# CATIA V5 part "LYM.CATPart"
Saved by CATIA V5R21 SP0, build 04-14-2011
Part number: LYM.SLDPRT
Bounding box of the stored display mesh (mm): x -1.375 to 1.375, y -1 to 1, z -0.25 to 0.45
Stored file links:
  C:\Users\user\Desktop\CATIA文件\LYM\LYM.CATPart
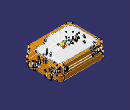
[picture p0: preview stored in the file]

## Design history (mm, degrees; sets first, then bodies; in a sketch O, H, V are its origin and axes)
AxisSystem1: origin (0.0446, -0.0275, 0.449), X (0, -1, 0), Y (1, 0, 0), Z (0, 0, 1)
Set1
  DatumSurface1 to DatumSurface42
  Circle1: stored without definition
  Line1: stored without definition
  Circle2: stored without definition
  Line2: stored without definition
  Circle3: stored without definition
  Line3: stored without definition
  Circle4: stored without definition
  Line4 to Line12: stored without definition
  Circle5: stored without definition
  Line13 to Line27: stored without definition
  Circle6: stored without definition
  Line28: stored without definition
  Circle7: stored without definition
  Line29: stored without definition
  Circle8: stored without definition
  Line30 to Line32: stored without definition
  Circle9: stored without definition
  Line33: stored without definition
  Circle10: stored without definition
  Line34 to Line40: stored without definition
  Circle11: stored without definition
  Line41: stored without definition
  Circle12: stored without definition
  Line42: stored without definition
  Circle13: stored without definition
  Line43: stored without definition
  Circle14: stored without definition
  Line44: stored without definition
  Line45: stored without definition
  Circle15: stored without definition
  Line46: stored without definition
  Circle16: stored without definition
  Line47: stored without definition
  Circle17: stored without definition
  Line48: stored without definition
  Circle18: stored without definition
  Line49: stored without definition
  Circle19: stored without definition
  Line50: stored without definition
  Circle20: stored without definition
  Line51: stored without definition
  Circle21: stored without definition
  Line52: stored without definition
  Circle22: stored without definition
  Line53 to Line56: stored without definition
  Circle23: stored without definition
  Line57 to Line59: stored without definition
  Circle24: stored without definition
  Line60 to Line62: stored without definition
  Circle25: stored without definition
  Line63 to Line65: stored without definition
  Circle26: stored without definition
  Line66 to Line69: stored without definition
  Circle27: stored without definition
  Line70 to Line72: stored without definition
  Circle28: stored without definition
  Line73: stored without definition
  Line74: stored without definition
  Circle29: stored without definition
  Line75 to Line77: stored without definition
  Circle30: stored without definition
  Line78 to Line82: stored without definition
  Circle31: stored without definition
  Line83: stored without definition
  Line84: stored without definition
  Circle32: stored without definition
  Line85 to Line88: stored without definition
  DatumSurface43 to DatumSurface82
  Line89 to Line104: stored without definition
  Circle33: stored without definition
  Line105 to Line122: stored without definition
  Circle34: stored without definition
  Circle35: stored without definition
  Line123: stored without definition
  Circle36: stored without definition
  Line124 to Line127: stored without definition
  Circle37: stored without definition
  Line128: stored without definition
  Circle38: stored without definition
  Line129 to Line135: stored without definition
  Circle39: stored without definition
  Line136: stored without definition
  Circle40: stored without definition
  Line137: stored without definition
  Circle41: stored without definition
  Line138: stored without definition
  Circle42: stored without definition
  Line139: stored without definition
  Line140: stored without definition
  Circle43: stored without definition
  Line141: stored without definition
  Circle44: stored without definition
  Line142: stored without definition
  Circle45: stored without definition
  Line143: stored without definition
  Circle46: stored without definition
  Line144: stored without definition
  Circle47: stored without definition
  Line145: stored without definition
  Circle48: stored without definition
  Line146: stored without definition
  Circle49: stored without definition
  Line147: stored without definition
  Circle50: stored without definition
  Line148: stored without definition
  Circle51: stored without definition
  Line149: stored without definition
  Circle52: stored without definition
  Line150: stored without definition
  Circle53: stored without definition
  Line151: stored without definition
  Circle54: stored without definition
  Line152: stored without definition
  Circle55: stored without definition
  Line153: stored without definition
  Circle56: stored without definition
  Line154: stored without definition
  Circle57: stored without definition
  Line155: stored without definition
  Circle58: stored without definition
  Line156 to Line176: stored without definition
  DatumSurface83 to DatumSurface188
  Line177: stored without definition
  Circle59: stored without definition
  Line178: stored without definition
  Circle60: stored without definition
  Line179: stored without definition
  Circle61: stored without definition
  Line180: stored without definition
  Circle62: stored without definition
  Line181 to Line197: stored without definition
  Circle63: stored without definition
  Line198 to Line214: stored without definition
  Circle64: stored without definition
  Line215: stored without definition
  Circle65: stored without definition
  Line216: stored without definition
  Circle66: stored without definition
  Line217 to Line220: stored without definition
  Circle67: stored without definition
  Circle68: stored without definition
  Line221 to Line227: stored without definition
  Circle69: stored without definition
  Line228: stored without definition
  Circle70: stored without definition
  Line229: stored without definition
  Circle71: stored without definition
  Line230: stored without definition
  Circle72: stored without definition
  Line231 to Line235: stored without definition
  Circle73: stored without definition
  Line236 to Line238: stored without definition
  Circle74: stored without definition
  Line239: stored without definition
  Circle75: stored without definition
  Line240 to Line242: stored without definition
  Circle76: stored without definition
  Line243 to Line249: stored without definition
  Circle77: stored without definition
  Circle78: stored without definition
  Line250 to Line256: stored without definition
  Circle79 to Circle81: stored without definition
  Line257: stored without definition
  Circle82: stored without definition
  Circle83: stored without definition
  Line258: stored without definition
  Circle84: stored without definition
  Line259 to Line266: stored without definition
  Circle85: stored without definition
  Line267 to Line281: stored without definition
  Circle86: stored without definition
  Line282: stored without definition
  Line283: stored without definition
  Circle87: stored without definition
  Line284: stored without definition
  Circle88: stored without definition
  Line285 to Line288: stored without definition
  Circle89: stored without definition
  Circle90: stored without definition
  Line289 to Line295: stored without definition
  Circle91: stored without definition
  Line296: stored without definition
  Circle92: stored without definition
  Line297: stored without definition
  Circle93: stored without definition
  Line298: stored without definition
  Circle94: stored without definition
  Line299 to Line302: stored without definition
  Circle95: stored without definition
  Line303 to Line305: stored without definition
  Circle96: stored without definition
  Line306 to Line309: stored without definition
  Circle97: stored without definition
  Line310: stored without definition
  Circle98: stored without definition
  Line311: stored without definition
  Circle99: stored without definition
  Line312: stored without definition
  Circle100: stored without definition
  Line313 to Line316: stored without definition
  Circle101: stored without definition
  Line317 to Line319: stored without definition
  Circle102: stored without definition
  Line320 to Line325: stored without definition
  Circle103: stored without definition
  Circle104: stored without definition
  Line326 to Line332: stored without definition
  Circle105: stored without definition
  Line333: stored without definition
  DatumCurve1
  Line334: stored without definition
  DatumCurve2
  Line335: stored without definition
  Line336: stored without definition
  DatumCurve3
  Line337: stored without definition
  DatumCurve4
  Line338 to Line340: stored without definition
  Circle106: stored without definition
  Circle107: stored without definition
  Line341: stored without definition
  DatumCurve5
  Line342: stored without definition
  DatumCurve6
  Line343: stored without definition
  Line344: stored without definition
  Circle108: stored without definition
  Line345: stored without definition
  DatumCurve7
  Line346: stored without definition
  DatumCurve8
  Line347 to Line360: stored without definition
  DatumCurve9
  Line361: stored without definition
  DatumCurve10
  Line362: stored without definition
  DatumCurve11
  Line363: stored without definition
  DatumCurve12
  Line364: stored without definition
  DatumCurve13
  Line365: stored without definition
  DatumCurve14
  Line366 to Line371: stored without definition
  DatumCurve15
  Line372 to Line375: stored without definition
  DatumCurve16
  Line376 to Line378: stored without definition
  DatumCurve17
  Line379 to Line381: stored without definition
  DatumCurve18
  Line382 to Line384: stored without definition
  DatumCurve19
  Line385 to Line387: stored without definition
  DatumCurve20
  Line388 to Line400: stored without definition
  DatumSurface189
  DatumCurve21
  Line401: stored without definition
  Point1 "发光中心（测试原点）": type Between, FirstPoint vertex of Line389, SecondPoint vertex of Line391, Ratio 0.5
  Point2 "几何中心": stored without definition
  Point3 "虚拟坐标": (-0.0115, -0.0275, -0.1181), relative to Point1, in AxisSystem1
Body1 (main body)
